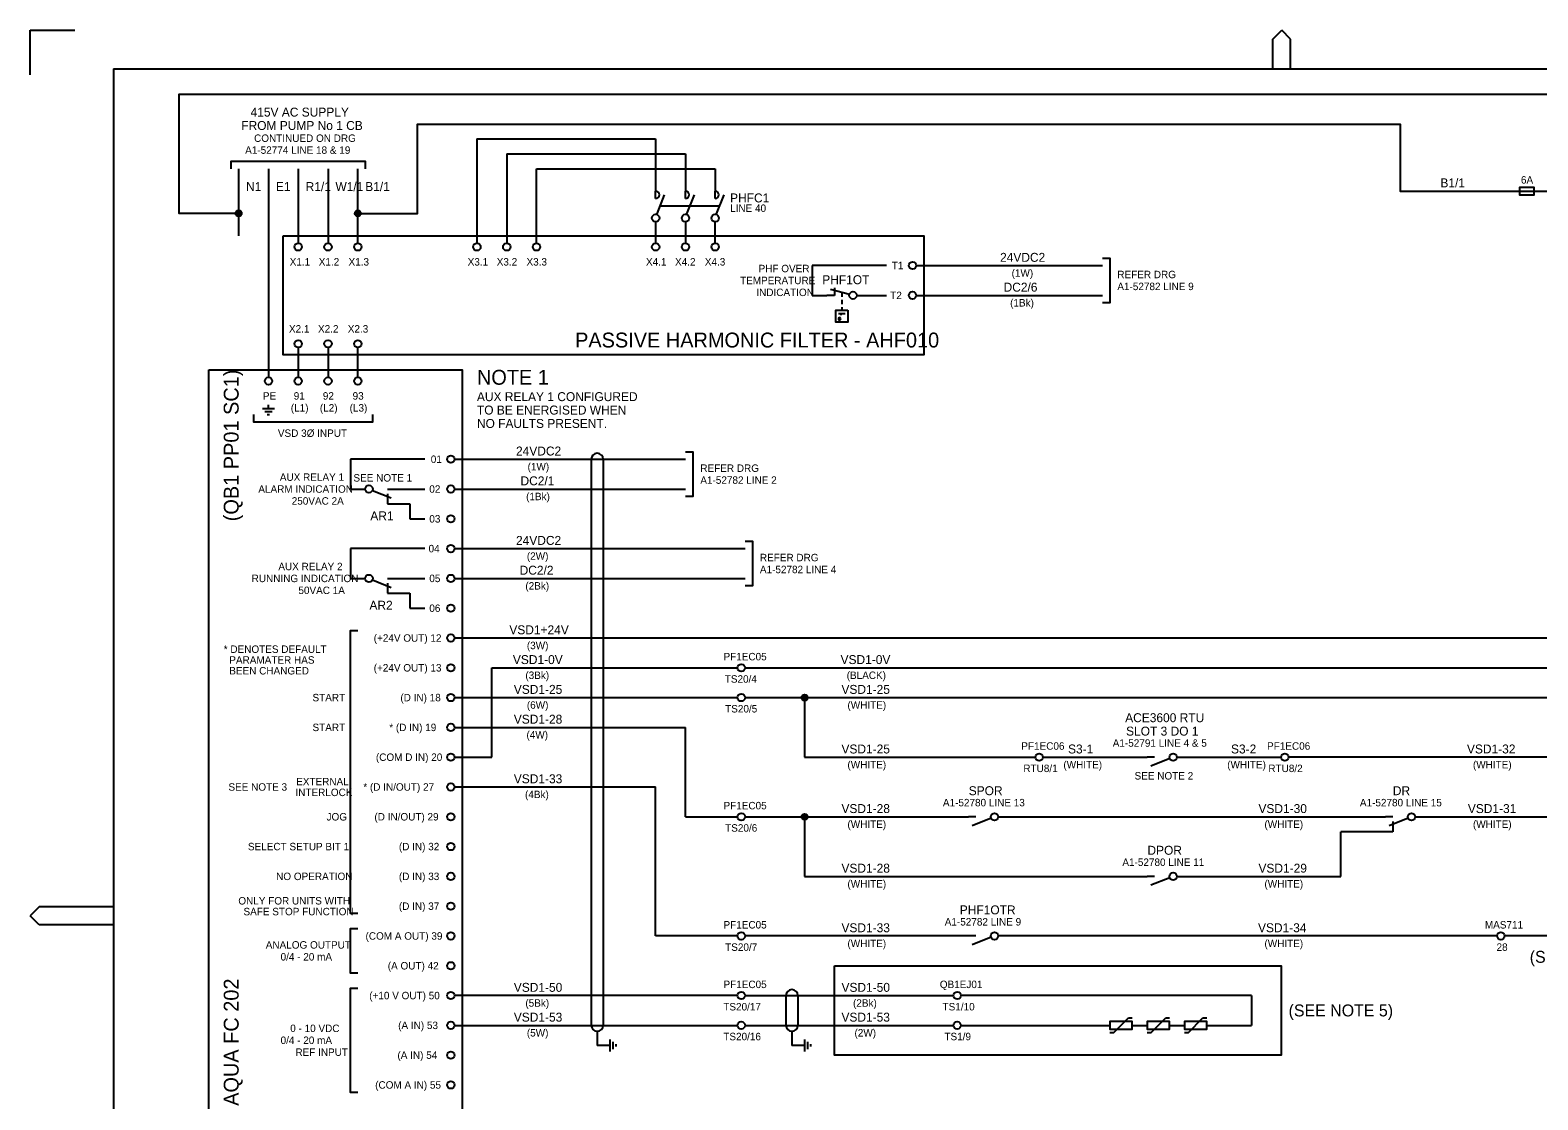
# Model space of a CAD drawing. Extents: x 0 to 841, y 0 to 594.
# Drawn here: x 0 to 506, y 235 to 594 of the extents above; entities that cross this region are included whole.
import ezdxf

# ---------------------------------------------------------------- set-up
doc = ezdxf.new("R2010")
doc.units = 0
for name, color, linetype in [('A1BORDER', 7, 'Continuous'), ('BASE', 7, 'Continuous'), ('Level 1', 7, 'Continuous'), ('Level 10', 7, 'Continuous'), ('Level 4', 7, 'Continuous'), ('Level 5', 7, 'Continuous'), ('Level 6', 7, 'Continuous')]:
    doc.layers.add(name, color=color, linetype=linetype)

msp = doc.modelspace()

# ---------------------------------------------------------------- linework, layer by layer
at = {"layer": 'A1BORDER'}
for p, q in [((0, 594), (15, 594)), ((0, 579), (0, 594)), ((417.19, 591), (420.19, 594)), ((423.19, 591), (420.19, 594)), ((417.19, 581), (417.19, 591)), ((423.19, 581), (423.19, 591)), ((28, 581), (829, 581)), ((28, 581), (28, 15)), ((3, 299.76), (0, 296.76)), ((28, 299.76), (3, 299.76)), ((3, 293.76), (0, 296.76)), ((28, 293.76), (3, 293.76))]:
    msp.add_line(p, q, dxfattribs=at)
at = {"layer": 'BASE'}
for p, q in [((188.37, 450), (188.37, 260)), ((192.37, 450), (192.37, 260)), ((253.75, 270), (253.75, 260)), ((257.75, 270), (257.75, 260)), ((190.37, 258), (190.37, 253.25)), ((194.74, 253.25), (190.37, 253.25)), ((255.75, 258), (255.75, 253.25)), ((260.12, 253.25), (255.75, 253.25))]:
    msp.add_line(p, q, dxfattribs=at)
for centre, start, end in [((190.37, 450), 0, 180), ((255.75, 270), 0, 180), ((190.37, 260), 180, 0), ((255.75, 260), 180, 0)]:
    msp.add_arc(centre, 2, start, end, dxfattribs=at)
at = {"layer": 'Level 1'}
for p, q in [((150, 557.5), (150, 522.5)), ((150, 557.5), (210, 557.5)), ((160, 552.5), (160, 522.5)), ((160, 552.5), (220, 552.5)), ((90, 547.5), (90, 522.5)), ((100, 547.5), (100, 522.5)), ((110, 522.5), (110, 547.5)), ((170, 522.5), (170, 547.5)), ((170, 547.5), (230, 547.5)), ((210, 537.5), (210, 540)), ((210.46, 532.41), (213, 538.75)), ((220, 537.5), (220, 540)), ((220.46, 532.41), (223, 538.75)), ((230, 537.5), (230, 540)), ((230.46, 532.41), (233, 538.75)), ((211.5, 535), (231.5, 535)), ((210, 529.69), (210, 522.5)), ((220, 529.69), (220, 522.5)), ((230, 522.5), (230, 529.69)), ((262.5, 515), (262.5, 505)), ((287.5, 515), (262.5, 515)), ((262.5, 505), (267.5, 505)), ((270, 505), (267.5, 505)), ((267.5, 505), (267.5, 505)), ((272.5, 506), (272.5, 504.5)), ((272.5, 503.5), (272.5, 502)), ((277.5, 505), (287.5, 505)), ((277.5, 505), (277.5, 505)), ((272.5, 501), (272.5, 500)), ((90, 487.5), (90, 477.5)), ((100, 487.5), (100, 477.5)), ((110, 477.5), (110, 487.5)), ((80, 467), (80, 468.25)), ((132.5, 450), (107.5, 450)), ((107.5, 450), (107.5, 440)), ((107.5, 440), (112.5, 440)), ((112.5, 440), (112.5, 440)), ((122.5, 440), (122.5, 440)), ((122.5, 440), (132.5, 440)), ((122.5, 435), (127.5, 435)), ((127.5, 435), (127.5, 430)), ((127.5, 430), (132.5, 430)), ((132.5, 420), (107.5, 420)), ((107.5, 420), (107.5, 410)), ((107.5, 410), (112.5, 410)), ((112.5, 410), (112.5, 410)), ((122.5, 410), (122.5, 410)), ((122.5, 410), (132.5, 410)), ((122.5, 405), (127.5, 405)), ((127.5, 405), (127.5, 400)), ((127.5, 400), (132.5, 400)), ((155, 350), (155, 380)), ((260, 370), (260, 350)), ((220, 330), (220, 360)), ((377.5, 350), (375, 350)), ((545, 350), (422.5, 350)), ((142.5, 340), (210, 340)), ((210, 290), (210, 340)), ((260, 330), (260, 310)), ((317.5, 330), (315, 330)), ((455, 325), (440, 325)), ((440, 310), (440, 325)), ((377.5, 310), (375, 310)), ((237.5, 290), (210, 290)), ((315, 290), (240, 290)), ((317.5, 290), (315, 290)), ((492.5, 290), (325, 290)), ((515, 290), (495, 290)), ((237.5, 270), (142.5, 270)), ((410, 270), (312.5, 270)), ((410, 270), (410, 260)), ((142.5, 260), (237.5, 260)), ((312.5, 260), (362.5, 260)), ((363.75, 257.5), (368.75, 262.5)), ((368.75, 262.5), (370, 262.5)), ((370, 260), (375, 260)), ((376.25, 257.5), (381.25, 262.5)), ((381.25, 262.5), (382.5, 262.5)), ((382.5, 260), (387.5, 260)), ((388.75, 257.5), (393.75, 262.5)), ((393.75, 262.5), (395, 262.5)), ((395, 260), (410, 260)), ((363.75, 257.5), (362.5, 257.5)), ((376.25, 257.5), (375, 257.5)), ((388.75, 257.5), (387.5, 257.5))]:
    msp.add_line(p, q, dxfattribs=at)
for points in [[(70, 532.5), (50, 532.5), (50, 572.5), (680, 572.5), (680, 540), (637.5, 540)], [(110, 532.5), (130, 532.5), (130, 562.5), (460, 562.5), (460, 540), (562.5, 540)], [(67.5, 547.5), (67.5, 550), (112.5, 550), (112.5, 547.5)], [(360, 517.5), (362.5, 517.5), (362.5, 502.5), (360, 502.5)], [(271.37, 498.87), (273.63, 498.87)], [(272.12, 497.14), (272.08, 497.32), (271.94, 497.45), (271.74, 497.51), (271.56, 497.45), (271.43, 497.32), (271.37, 497.14), (271.43, 496.94), (271.56, 496.8), (271.74, 496.76), (271.94, 496.8), (272.08, 496.94), (272.12, 497.14)], [(272.12, 499.12), (272.12, 498.37)], [(75, 465), (75, 462.5), (115, 462.5), (115, 465)], [(220, 452.5), (222.5, 452.5), (222.5, 437.5), (220, 437.5)], [(240, 422.5), (242.5, 422.5), (242.5, 407.5), (240, 407.5)], [(110, 297.5), (107.5, 297.5), (107.5, 392.5), (110, 392.5)], [(110, 277.5), (107.5, 277.5), (107.5, 292.5), (110, 292.5)], [(110, 237.5), (107.5, 237.5), (107.5, 272.5), (110, 272.5)]]:
    msp.add_lwpolyline(points, dxfattribs=at)
for points in [[(85, 525), (300, 525), (300, 485), (85, 485)], [(274.5, 500), (274.5, 496), (270.5, 496), (270.5, 500)], [(60, 480), (145, 480), (145, 160), (60, 160)], [(270, 280), (420, 280), (420, 250), (270, 250)]]:
    msp.add_lwpolyline(points, close=True, dxfattribs=at)
for centre in [(210, 530.94), (220, 530.94), (230, 530.94)]:
    msp.add_circle(centre, 1.25, dxfattribs=at)
for centre in [(210, 538.75), (220, 538.75), (230, 538.75)]:
    msp.add_arc(centre, 1.25, 270, 90, dxfattribs=at)
at = {"layer": 'Level 10'}
for p, q in [((69, 532.5), (69, 532.5)), ((69.1, 532.06), (69.1, 532.94)), ((69.4, 531.7), (69.4, 533.3)), ((69.7, 531.55), (69.7, 533.45)), ((70, 531.5), (70, 533.49)), ((70.3, 531.55), (70.3, 533.45)), ((70.6, 531.7), (70.6, 533.3)), ((70.9, 532.06), (70.9, 532.94)), ((109, 532.5), (109, 532.5)), ((109.1, 532.06), (109.1, 532.94)), ((109.4, 531.7), (109.4, 533.3)), ((109.7, 531.55), (109.7, 533.45)), ((110, 531.5), (110, 533.49)), ((110.3, 531.55), (110.3, 533.45)), ((110.6, 531.7), (110.6, 533.3)), ((110.9, 532.06), (110.9, 532.94)), ((275.04, 505.32), (268.75, 507)), ((270, 507.5), (270, 505)), ((78, 467), (82, 467)), ((78.8, 466), (81.2, 466)), ((79.6, 465), (80.4, 465)), ((114.91, 439.54), (121.25, 437)), ((120, 440), (122.5, 440)), ((120, 438.37), (120, 435)), ((120, 435), (122.5, 435)), ((114.91, 409.54), (121.25, 407)), ((120, 410), (122.5, 410)), ((120, 408.37), (120, 405)), ((120, 405), (122.5, 405)), ((259, 370), (259, 370)), ((259.1, 369.56), (259.1, 370.44)), ((259.4, 369.2), (259.4, 370.8)), ((259.7, 369.05), (259.7, 370.95)), ((260, 369), (260, 370.99)), ((260.3, 369.05), (260.3, 370.95)), ((260.6, 369.2), (260.6, 370.8)), ((260.9, 369.56), (260.9, 370.44)), ((382.59, 349.54), (376.25, 347)), ((259, 330), (259, 330)), ((259.1, 329.56), (259.1, 330.44)), ((259.4, 329.2), (259.4, 330.8)), ((259.7, 329.05), (259.7, 330.95)), ((260, 329), (260, 330.99)), ((260.3, 329.05), (260.3, 330.95)), ((260.6, 329.2), (260.6, 330.8)), ((260.9, 329.56), (260.9, 330.44)), ((322.59, 329.54), (316.25, 327)), ((457.5, 330), (455, 330)), ((462.59, 329.54), (456.25, 327)), ((457.5, 325), (455, 325)), ((457.5, 328.37), (457.5, 325)), ((382.59, 309.54), (376.25, 307)), ((322.59, 289.54), (316.25, 287)), ((194.74, 251.25), (194.74, 255.25)), ((195.74, 252.05), (195.74, 254.45)), ((196.74, 252.85), (196.74, 253.65)), ((260.12, 251.25), (260.12, 255.25)), ((261.12, 252.05), (261.12, 254.45)), ((262.12, 252.85), (262.12, 253.65))]:
    msp.add_line(p, q, dxfattribs=at)
for points in [[(505, 540), (505, 541.25), (500, 541.25), (500, 538.75), (505, 538.75), (505, 540)], [(362.5, 260), (362.5, 258.75), (370, 258.75), (370, 261.25), (362.5, 261.25), (362.5, 260)], [(375, 260), (375, 258.75), (382.5, 258.75), (382.5, 261.25), (375, 261.25), (375, 260)], [(387.5, 260), (387.5, 258.75), (395, 258.75), (395, 261.25), (387.5, 261.25), (387.5, 260)]]:
    msp.add_lwpolyline(points, dxfattribs=at)
for centre, radius in [((70, 532.5), 1), ((110, 532.5), 1), ((276.25, 505), 1.25), ((113.75, 440), 1.25), ((113.75, 410), 1.25), ((260, 370), 1), ((383.75, 350), 1.25), ((260, 330), 1), ((323.75, 330), 1.25), ((463.75, 330), 1.25), ((383.75, 310), 1.25), ((323.75, 290), 1.25)]:
    msp.add_circle(centre, radius, dxfattribs=at)
at = {"layer": 'Level 4'}
for centre in [(90, 521.25), (100, 521.25), (110, 521.25), (150, 521.25), (160, 521.25), (170, 521.25), (210, 521.25), (220, 521.25), (230, 521.25), (90, 488.75), (100, 488.75), (110, 488.75), (80, 476.25), (90, 476.25), (100, 476.25), (110, 476.25)]:
    msp.add_circle(centre, 1.25, dxfattribs=at)
at = {"layer": 'Level 5'}
for p, q in [((210, 557.5), (210, 540)), ((220, 552.5), (220, 540)), ((70, 547.5), (70, 525)), ((80, 547.5), (80, 477.5)), ((230, 547.5), (230, 540))]:
    msp.add_line(p, q, dxfattribs=at)
for centre in [(296.25, 515), (296.25, 505), (141.25, 450), (141.25, 440), (141.25, 430), (141.25, 420), (141.25, 410), (141.25, 400), (141.25, 390), (141.25, 380), (238.75, 380), (141.25, 370), (238.75, 370), (141.25, 360), (141.25, 350), (338.75, 350), (421.25, 350), (141.25, 340), (141.25, 330), (238.75, 330), (141.25, 320), (141.25, 310), (141.25, 300), (141.25, 290), (238.75, 290), (493.75, 290), (141.25, 280), (141.25, 270), (238.75, 270), (311.25, 270), (141.25, 260), (238.75, 260), (311.25, 260), (141.25, 250), (141.25, 240)]:
    msp.add_circle(centre, 1.25, dxfattribs=at)
at = {"layer": 'Level 6'}
for p, q in [((297.5, 515), (360, 515)), ((297.5, 505), (360, 505)), ((142.5, 450), (220, 450)), ((142.5, 440), (220, 440)), ((142.5, 420), (240, 420)), ((142.5, 410), (240, 410)), ((142.5, 390), (680, 390)), ((155, 380), (237.5, 380)), ((240, 380), (720, 380)), ((142.5, 370), (237.5, 370)), ((240, 370), (590, 370)), ((142.5, 360), (220, 360)), ((142.5, 350), (155, 350)), ((260, 350), (337.5, 350)), ((340, 350), (375, 350)), ((385, 350), (420, 350)), ((220, 330), (237.5, 330)), ((240, 330), (315, 330)), ((325, 330), (455, 330)), ((465, 330), (515, 330)), ((260, 310), (375, 310)), ((385, 310), (440, 310)), ((240, 270), (310, 270)), ((240, 260), (310, 260))]:
    msp.add_line(p, q, dxfattribs=at)

# ---------------------------------------------------------------- texts
at = {"layer": 'Level 1'}
for s, height, p in [('CONTINUED ON DRG', 2.5, (75.18, 556.5)), ('A1-52774 LINE 18 & 19', 2.5, (72.19, 552.5)), ('N1', 3, (72.5, 540)), ('E1', 3, (82.5, 540)), ('R1/1', 3, (92.5, 540)), ('W1/1', 3, (102.5, 540)), ('B1/1', 3, (112.5, 540)), ('PHFC1', 3, (235, 536.19)), ('LINE 40', 2.5, (235, 533)), ('X1.1', 2.5, (87.14, 515)), ('X1.2', 2.5, (96.89, 515)), ('X1.3', 2.5, (106.89, 515)), ('X3.1', 2.5, (146.89, 515)), ('X3.2', 2.5, (156.64, 515)), ('X3.3', 2.5, (166.64, 515)), ('X4.1', 2.5, (206.76, 515)), ('X4.2', 2.5, (216.51, 515)), ('X4.3', 2.5, (226.51, 515)), ('TEMPERATURE', 2.5, (238.33, 508.75)), ('PHF OVER', 2.5, (244.56, 512.75)), ('T1', 2.5, (289.26, 513.75)), ('REFER DRG', 2.5, (365, 510.75)), ('INDICATION', 2.5, (243.81, 504.75)), ('T2', 2.5, (288.76, 503.75)), ('A1-52782 LINE 9', 2.5, (365, 506.75)), ('X2.1', 2.5, (86.89, 492.5)), ('X2.2', 2.5, (96.64, 492.5)), ('X2.3', 2.5, (106.64, 492.5)), ('PASSIVE HARMONIC FILTER - AHF010', 5, (182.95, 487.5)), ('NOTE 1', 5, (150, 475)), ('PE', 2.5, (78.13, 470)), ('91', 2.5, (88.5, 470)), ('92', 2.5, (98.26, 470)), ('93', 2.5, (108.26, 470)), ('AUX RELAY 1 CONFIGURED', 3, (150, 469.5)), ('(L1)', 2.5, (87.51, 465.99)), ('(L2)', 2.5, (97.26, 465.99)), ('(L3)', 2.5, (107.26, 465.99)), ('TO BE ENERGISED WHEN', 3, (150, 465)), ('NO FAULTS PRESENT.', 3, (150, 460.5)), ('VSD 3Ø INPUT', 2.5, (83.17, 457.5)), ('01', 2.5, (134.51, 448.75)), ('REFER DRG', 2.5, (225, 445.75)), ('ALARM INDICATION', 2.5, (76.61, 438.75)), ('AUX RELAY 1', 2.5, (83.83, 442.75)), ('SEE NOTE 1', 2.5, (108.54, 442.5)), ('02', 2.5, (134.01, 438.75)), ('A1-52782 LINE 2', 2.5, (225, 441.75)), ('250VAC 2A', 2.5, (87.82, 434.75)), ('03', 2.5, (134.01, 428.75)), ('04', 2.5, (133.76, 418.75)), ('AUX RELAY 2', 2.5, (83.33, 412.75)), ('REFER DRG', 2.5, (245, 415.75)), ('RUNNING INDICATION', 2.5, (74.37, 408.75)), ('05', 2.5, (134.01, 408.75)), ('A1-52782 LINE 4', 2.5, (245, 411.75)), ('50VAC 1A', 2.5, (90.06, 404.75)), ('06', 2.5, (134.01, 398.75)), ('(+24V OUT) 12', 2.5, (115.34, 388.75)), ('* DENOTES DEFAULT', 2.5, (65, 385)), ('PF1EC05', 2.5, (232.78, 382.5)), ('  PARAMATER HAS', 2.5, (65, 381.38)), ('  BEEN CHANGED', 2.5, (65, 377.76)), ('(+24V OUT) 13', 2.5, (115.34, 378.75)), ('START', 2.5, (94.79, 368.75)), ('(D IN) 18', 2.5, (124.3, 368.75)), ('START', 2.5, (94.79, 358.75)), ('* (D IN) 19', 2.5, (120.56, 358.75)), ('PF1EC06', 2.5, (332.77, 352.5)), ('PF1EC06', 2.5, (415.27, 352.5)), ('(COM D IN) 20', 2.5, (116.08, 348.75)), ('SEE NOTE 3', 2.5, (66.57, 338.75)), ('INTERLOCK', 2.5, (89.07, 336.94)), ('EXTERNAL', 2.5, (89.31, 340.56)), ('* (D IN/OUT) 27', 2.5, (111.85, 338.75)), ('PF1EC05', 2.5, (232.78, 332.5)), ('JOG', 2.5, (99.52, 328.75)), ('(D IN/OUT) 29', 2.5, (115.58, 328.75)), ('SELECT SETUP BIT 1', 2.5, (73.12, 318.75)), ('(D IN) 32', 2.5, (123.8, 318.75)), ('NO OPERATION', 2.5, (82.59, 308.75)), ('(D IN) 33', 2.5, (123.8, 308.75)), ('ONLY FOR UNITS WITH', 2.5, (69.89, 300.56)), ('SAFE STOP FUNCTION', 2.5, (71.63, 296.94)), ('(D IN) 37', 2.5, (123.8, 298.75)), ('PF1EC05', 2.5, (232.78, 292.5)), ('MAS711', 2.5, (488.4, 292.5)), ('(COM A OUT) 39', 2.5, (112.6, 288.75)), ('ANALOG OUTPUT', 2.5, (79.1, 285.75)), ('0/4 - 20 mA', 2.5, (84.08, 281.75)), ('(SEE NOTE 4)', 4, (503.46, 281)), ('(A OUT) 42', 2.5, (120.07, 278.75)), ('PF1EC05', 2.5, (232.78, 272.5)), ('QB1EJ01', 2.5, (305.4, 272.5)), ('(+10 V OUT) 50', 2.5, (113.84, 268.75)), ('(SEE NOTE 5)', 4, (422.5, 263)), ('0 - 10 VDC', 2.5, (87.32, 257.75)), ('(A IN) 53', 2.5, (123.55, 258.75)), ('0/4 - 20 mA', 2.5, (84.08, 253.75)), ('REF INPUT', 2.5, (89.06, 249.75)), ('(A IN) 54', 2.5, (123.31, 248.75)), ('(COM A IN) 55', 2.5, (115.83, 238.75))]:
    msp.add_text(s, height=height, dxfattribs=at).set_placement(p)
for s, p in [('(QB1 PP01 SC1)', (70, 429.18)), ('VSD - DANFOSS VLT AQUA FC 202', (70, 165))]:
    msp.add_text(s, height=5, rotation=90, dxfattribs=at).set_placement(p)
at = {"layer": 'Level 5'}
for s, height, p in [('415V AC SUPPLY', 3, (74.01, 565)), ('FROM PUMP No 1 CB', 3, (70.88, 560.5)), ('B1/1', 3, (473.47, 541.25)), ('6A', 2.5, (500.51, 542.5)), ('24VDC2', 3, (325.63, 516.25)), ('PHF1OT', 3, (265.93, 508.75)), ('(1W)', 2.5, (329.51, 511.25)), ('DC2/6', 3, (326.82, 506.25)), ('(1Bk)', 2.5, (329.01, 501.25)), ('24VDC2', 3, (163.12, 451.25)), ('(1W)', 2.5, (167.01, 446.25)), ('DC2/1', 3, (164.63, 441.25)), ('(1Bk)', 2.5, (166.51, 436.25)), ('AR1', 3, (114.21, 429.5)), ('24VDC2', 3, (163.12, 421.25)), ('(2W)', 2.5, (166.76, 416.25)), ('DC2/2', 3, (164.33, 411.25)), ('(2Bk)', 2.5, (166.26, 406.25)), ('AR2', 3, (113.91, 399.5)), ('VSD1+24V', 3, (160.88, 391.25)), ('(3W)', 2.5, (166.76, 386.25)), ('VSD1-0V', 3, (162.07, 381.25)), ('VSD1-0V', 3, (272.08, 381.25)), ('(3Bk)', 2.5, (166.26, 376.25)), ('TS20/4', 2.5, (233.21, 375)), ('(BLACK)', 2.5, (274.14, 376.25)), ('VSD1-25', 3, (162.38, 371.25)), ('VSD1-25', 3, (272.38, 371.25)), ('(6W)', 2.5, (166.76, 366.25)), ('TS20/5', 2.5, (233.33, 365)), ('(WHITE)', 2.5, (274.39, 366.25)), ('ACE3600 RTU', 3, (367.64, 361.75)), ('VSD1-28', 3, (162.38, 361.25)), ('SLOT 3 DO 1', 3, (367.94, 357.25)), ('(4W)', 2.5, (166.63, 356.25)), ('A1-52791 LINE 4 & 5', 2.5, (363.46, 353.5)), ('VSD1-25', 3, (272.38, 351.25)), ('S3-1', 3, (348.46, 351.25)), ('S3-2', 3, (403.17, 351.25)), ('VSD1-32', 3, (482.38, 351.25)), ('VSD1-33', 3, (162.38, 341.25)), ('(WHITE)', 2.5, (274.39, 346.25)), ('RTU8/1', 2.5, (333.45, 345)), ('(WHITE)', 2.5, (346.89, 346.25)), ('SEE NOTE 2', 2.5, (370.79, 342.5)), ('(WHITE)', 2.5, (401.9, 346.25)), ('RTU8/2', 2.5, (415.71, 345)), ('(WHITE)', 2.5, (484.39, 346.25)), ('SPOR', 3, (315.11, 337.25)), ('DR', 3, (457.5, 337.25)), ('(4Bk)', 2.5, (166.14, 336.25)), ('VSD1-28', 3, (272.38, 331.25)), ('A1-52780 LINE 13', 2.5, (306.44, 333.5)), ('VSD1-30', 3, (412.38, 331.25)), ('A1-52780 LINE 15', 2.5, (446.44, 333.5)), ('VSD1-31', 3, (482.68, 331.25)), ('TS20/6', 2.5, (233.33, 325)), ('(WHITE)', 2.5, (274.39, 326.25)), ('(WHITE)', 2.5, (414.39, 326.25)), ('(WHITE)', 2.5, (484.39, 326.25)), ('DPOR', 3, (375.11, 317.25)), ('VSD1-28', 3, (272.38, 311.25)), ('A1-52780 LINE 11', 2.5, (366.69, 313.5)), ('VSD1-29', 3, (412.38, 311.25)), ('(WHITE)', 2.5, (274.39, 306.25)), ('(WHITE)', 2.5, (414.39, 306.25)), ('PHF1OTR', 3, (312.12, 297.25)), ('VSD1-33', 3, (272.38, 291.25)), ('A1-52782 LINE 9', 2.5, (307.06, 293.5)), ('VSD1-34', 3, (412.23, 291.25)), ('(WHITE)', 2.5, (274.39, 286.25)), ('(WHITE)', 2.5, (414.39, 286.25)), ('TS20/7', 2.5, (233.33, 285)), ('28', 2.5, (492.32, 285)), ('VSD1-50', 3, (162.38, 271.25)), ('VSD1-50', 3, (272.39, 271.25)), ('(5Bk)', 2.5, (166.26, 266.25)), ('(2Bk)', 2.5, (276.26, 266.25)), ('VSD1-53', 3, (162.38, 261.25)), ('TS20/17', 2.5, (232.71, 265)), ('VSD1-53', 3, (272.38, 261.25)), ('TS1/10', 2.5, (306.33, 265)), ('(5W)', 2.5, (166.76, 256.25)), ('(2W)', 2.5, (276.76, 256.25)), ('TS20/16', 2.5, (232.71, 255)), ('TS1/9', 2.5, (306.95, 255))]:
    msp.add_text(s, height=height, dxfattribs=at).set_placement(p)

doc.saveas('drawing.dxf')
